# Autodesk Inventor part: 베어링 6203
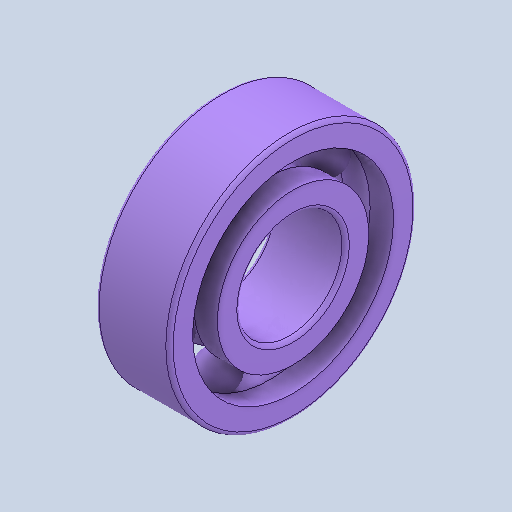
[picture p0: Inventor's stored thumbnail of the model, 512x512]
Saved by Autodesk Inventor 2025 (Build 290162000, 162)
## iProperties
Created: 2024-08
Part Number: 베어링 6203
Material: 스테인리스강
Description: 깊은 그루브 볼 베어링
Document SubType Name: Modeling
Designer: rese9
Density: 8.08 g/cm^3
Appearance: 기본값
Author: jhkim
Sending System: Autodesk Inventor 2025
Preprocessor: ST-DEVELOPER v20
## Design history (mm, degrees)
feature "Solid1"
feature "Solid1:1"
feature "Solid1:2"
feature "Solid1:3"
feature "Solid1:4"
feature "Solid1:5"
feature "Solid1:6"
feature "Solid1:7"
feature "Solid1:8"
node "솔리드1"
node "솔리드2"
node "솔리드3"
node "솔리드4"
node "솔리드5"
node "솔리드6"
node "솔리드7"
node "솔리드8"
node "솔리드9"
